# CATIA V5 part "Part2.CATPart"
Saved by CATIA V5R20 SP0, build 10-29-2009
Part number: p12
Bounding box of the stored display mesh (mm): x 0 to 5, y -54.999 to 44.992, z 55 to 65
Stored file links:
  D:\Dropbox\IAO_2011\MMS_GR2\IAO_2011_1439_jlicbarski\Part2.CATPart
  D:\Dropbox\IAO_2011\MMS_GR2\IAO_2011_1439_jlicbarski\train.CATProduct
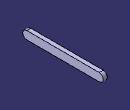
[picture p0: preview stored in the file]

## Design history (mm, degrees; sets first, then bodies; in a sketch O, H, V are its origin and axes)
AxisSystem1: origin (0, 0, 0), X (1, 0, 0), Y (0, 1, 0), Z (0, 0, 1)
Set1
  Plane1: linked copy from another document
  Line1: linked copy from another document
  Line2: linked copy from another document
Body1 (main body)
  Sketch1 on Plane1, origin (0, 0, 0), H (0, 1, 0), V (0, 0, 1)
    arc A1 centre (-50, 60) radius 5 from (-49.7479, 64.9936) to (-49.95, 55.0002) ccw
    arc A2 centre (40, 60) radius 5 from (39.9432, 55.0003) to (40, 65) ccw
    reference projected point E1 (40, 60) from Line1
    reference projected point E2 (-50, 60) from Line2
    line L1 (-49.7479, 64.9936) -> (40, 65)
    line L2 (39.9432, 55.0003) -> (-49.95, 55.0002)
    radius A2 = 5
    distance A2 E1 = 5
    radius A1 = 5
    distance A1 E2 = 5
    distance A2 A1 = 100
  Pad1: profile Sketch1, direction (1, 0, 0), length 5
